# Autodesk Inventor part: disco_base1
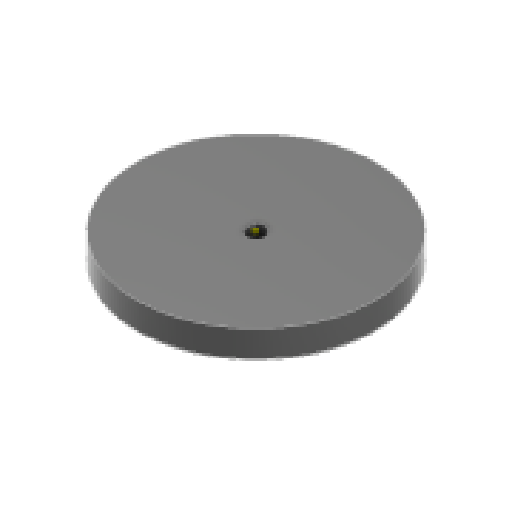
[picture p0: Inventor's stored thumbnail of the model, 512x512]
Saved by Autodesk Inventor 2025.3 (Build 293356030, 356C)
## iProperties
Created: 2026-03
Part Number: disco_base1
Material: Plastica ABS
Document SubType Name: Modeling
Designer: R5800u
Density: 1.06 g/cm^3
Appearance: Liscia - Nero
Author: R5800u
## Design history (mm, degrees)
sketch "Schizzo1"
  geometry: C1 r 10 at (0, 0); C2 r 50 at (0, 0); 1 further point
  constraints: 2 centre point, 2 coincident
  dimensions: "d0" = 20 diameter of C1; "d1" = 100 diameter of C2
extrude "Estrusione1" new body sketch "Schizzo1" distance "d2" = 12; taper "d3" = 0 deg
extrude "Estrusione2" join sketch "Schizzo1" distance "d4" = 6; taper "d5" = 0 deg
sketch "Schizzo3"
  geometry: C1 r 10 at (0, 0) reference; 2 further points
  constraints: 1 coincident
hole "Foro1" sketch "Schizzo3" at (0, 0) diameter "d6" = 8; stored, may be unused: countersink angle "d10" = 90 deg, drill point angle "d12" = 118 deg; dims "d7" = 6, "d8" = 6.5, "d9" = 4.6, "d11" = 11.8
sketch "Schizzo4"
  geometry: C1 r 4 at (0, 0) reference; C2 r 35 at (0, 0); C3 r 10 at (0, 0) reference; C4 r 10 at (0, 0) reference; C5 r 24.5 at (0, 0); 1 further point
  constraints: 2 centre point, 2 coincident
  dimensions: "d13" = 70 diameter of C2; "d16" = 49 diameter of C5
extrude "Estrusione3" cut sketch "Schizzo4" distance "d14" = 5; taper "d15" = 0 deg
fillet "Raccordo1" dims "d17" = 1
sketch "Schizzo5"
  geometry: 1 further point
sketch "Schizzo6"
  geometry: C1 r 3 at (30, -55) reference; C2 r 3 at (-30, -55) reference; C3 r 3 at (-30, 55) reference; C4 r 3 at (30, 55) reference; 1 further point
hole "Foro2" sketch "Schizzo6" at (-30, -55), (30, -55), (-30, 55), (30, 55) diameter "d18" = 4.3; stored, may be unused: countersink angle "d22" = 90 deg, drill point angle "d24" = 118 deg; dims "d19" = 6, "d20" = 8, "d21" = 4.6, "d23" = 8
sketch "Schizzo7" dims "d25" = 8.5, "d28" = 8.5, "d29" = 8.5, "d30" = 8.5
  geometry: L1 (-30, -50.75)-(-26.319, -52.875); L2 (-26.319, -52.875)-(-26.319, -57.125); L3 (-26.319, -57.125)-(-30, -59.25); L4 (-30, -59.25)-(-33.681, -57.125); L5 (-33.681, -57.125)-(-33.681, -52.875); L6 (-33.681, -52.875)-(-30, -50.75); L7 (-30, 59.25)-(-26.319, 57.125); L8 (-26.319, 57.125)-(-26.319, 52.875); L9 (-26.319, 52.875)-(-30, 50.75); L10 (-30, 50.75)-(-33.681, 52.875); L11 (-33.681, 52.875)-(-33.681, 57.125); L12 (-33.681, 57.125)-(-30, 59.25); L13 (30, 59.25)-(33.681, 57.125); L14 (33.681, 57.125)-(33.681, 52.875); L15 (33.681, 52.875)-(30, 50.75); L16 (30, 50.75)-(26.319, 52.875); L17 (26.319, 52.875)-(26.319, 57.125); L18 (26.319, 57.125)-(30, 59.25); L19 (30, -50.75)-(33.681, -52.875); L20 (33.681, -52.875)-(33.681, -57.125); L21 (33.681, -57.125)-(30, -59.25); L22 (30, -59.25)-(26.319, -57.125); L23 (26.319, -57.125)-(26.319, -52.875); L24 (26.319, -52.875)-(30, -50.75); C1 r 35 at (0, 0) reference; C2 r 49 at (0, 0) reference; 9 further points
  constraints: 48 end point, 4 coincident, 3 vertical alignment, 61 other
extrude "Estrusione4" cut sketch "Schizzo7" distance "d26" = 5; taper "d27" = 0 deg
sketch "Schizzo8"
  geometry: L1 (-3.1, -2.528)-(-3.1, 2.528); A1 r 4 centre (0, 0) between (-3.1, -2.528) and (-3.1, 2.528) reference; 1 further point
  constraints: 2 end point, 2 point on circle, 1 vertical
  dimensions: "d31" = 3.1 distance from line of point (0, 0) L1
extrude "Estrusione5" join sketch "Schizzo8" stored distance "d32" = 5; taper "d33" = 0 deg
node "Solido1"
node "Riferimento1"
node "Riferimento2"
node "Riferimento3"
node "Riferimento4"
node "Linea chiusa proiettata1"
